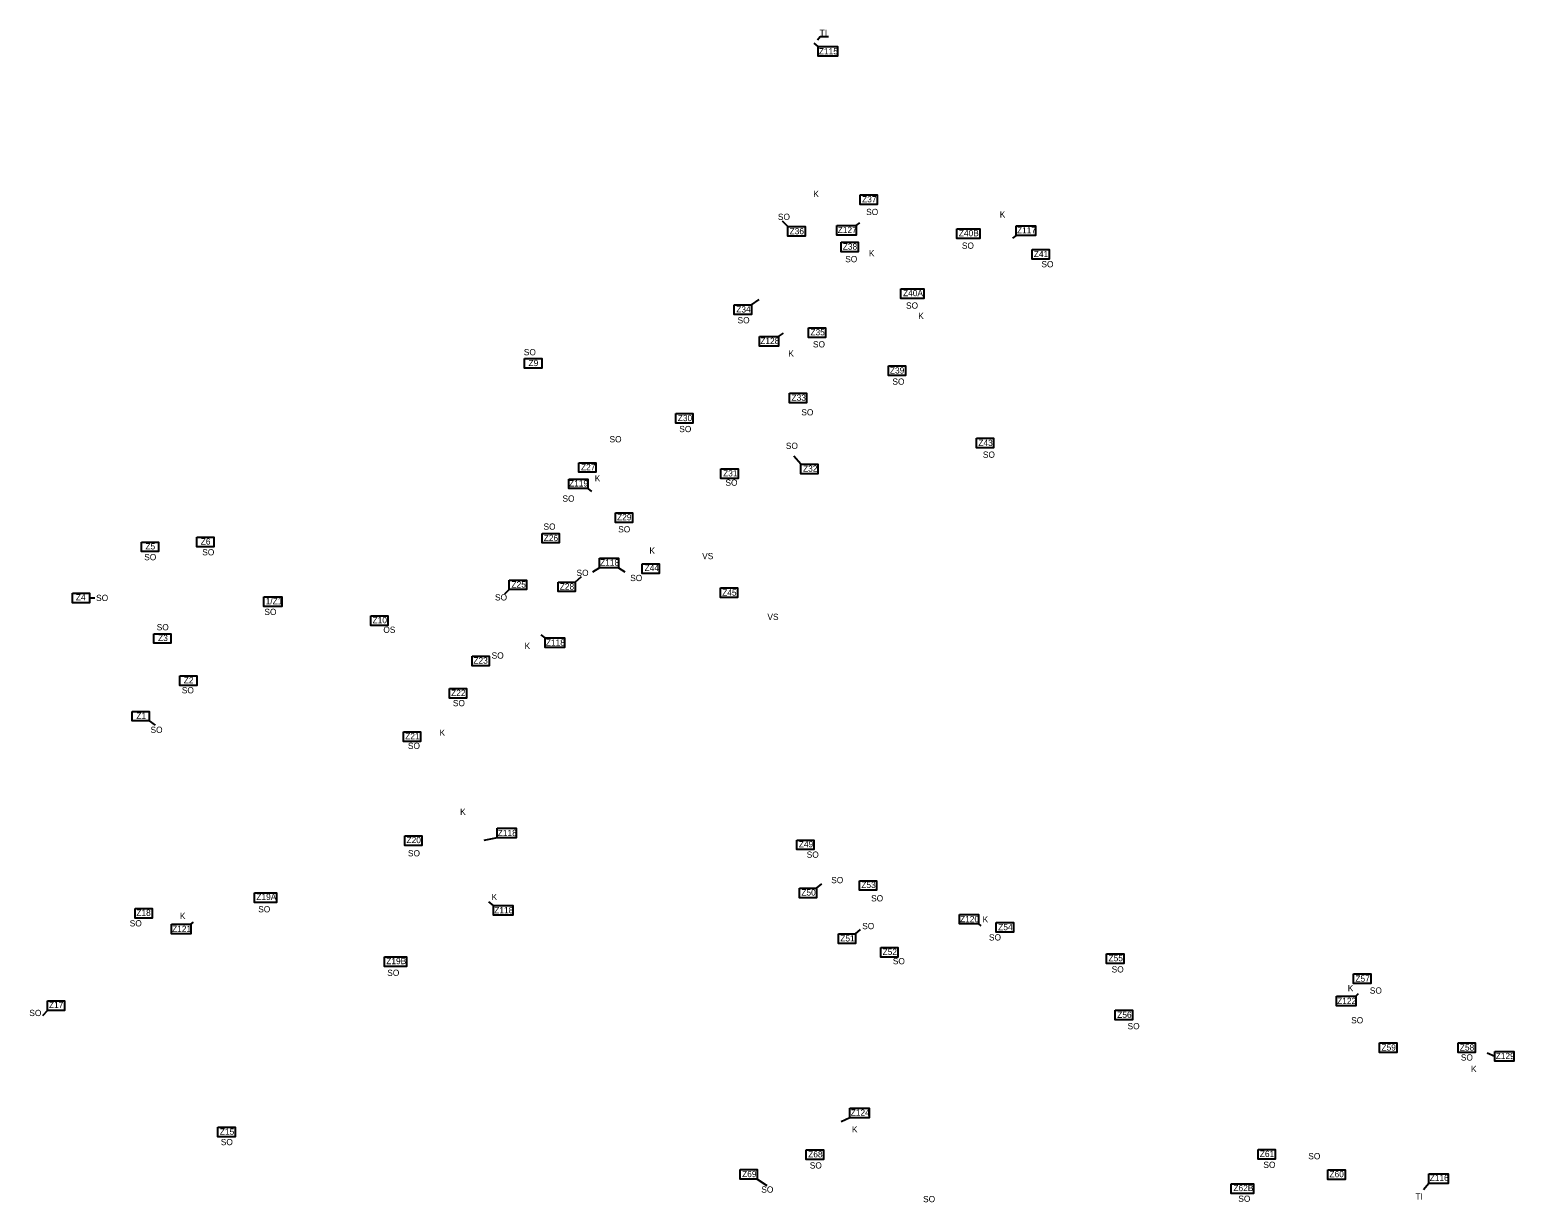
# Model space of a CAD drawing. Extents: x -443485 to -433023, y -1133480 to -1129775.
# Drawn here: x -443043 to -440666, y -1131652 to -1129775 of the extents above; entities that cross this region are included whole.
import ezdxf

# ---------------------------------------------------------------- set-up
doc = ezdxf.new("R2010")
doc.units = 0
for name, color, linetype in [('Vrstva 3', 7, 'Continuous'), ('Vrstva 4', 7, 'Continuous'), ('Vrstva 8', 7, 'Continuous')]:
    doc.layers.add(name, color=color, linetype=linetype)

msp = doc.modelspace()

# ---------------------------------------------------------------- linework, layer by layer
at = {"layer": 'Vrstva 3'}
for p, q in [((-441780.6, -1129802.1), (-441787.2, -1129796.7)), ((-441829.1, -1130090.3), (-441838, -1130081.7)), ((-441808.5, -1130470.4), (-441819.7, -1130457.7)), ((-442169.8, -1130659.1), (-442159.4, -1130650.4)), ((-442275.3, -1130671.3), (-442283.1, -1130678.3)), ((-442947.3, -1130684.5), (-442938.5, -1130684.6)), ((-442851.5, -1130881.4), (-442842.3, -1130888.4)), ((-441783.2, -1131148.9), (-441775.1, -1131141.9)), ((-441721, -1131222.3), (-441712.8, -1131215.4)), ((-443014.7, -1131344.8), (-443022.4, -1131353.5)), ((-441878.2, -1131614.7), (-441862.9, -1131625)), ((-440803, -1131621.5), (-440811.7, -1131631.9))]:
    msp.add_line(p, q, dxfattribs=at)
for points in [[(-441780.6, -1129802.1), (-441749.8, -1129802.1), (-441749.8, -1129817.5), (-441780.6, -1129817.5)], [(-441713.5, -1130039.3), (-441686.2, -1130039.3), (-441686.2, -1130054.7), (-441713.5, -1130054.7)], [(-441829.1, -1130090.3), (-441801.8, -1130090.3), (-441801.8, -1130105.7), (-441829.1, -1130105.7)], [(-441558.8, -1130093.8), (-441522, -1130093.8), (-441522, -1130109.2), (-441558.8, -1130109.2)], [(-441744, -1130115.3), (-441716.6, -1130115.3), (-441716.6, -1130130.7), (-441744, -1130130.7)], [(-441438.1, -1130126.8), (-441410.7, -1130126.8), (-441410.7, -1130142.2), (-441438.1, -1130142.2)], [(-441648.2, -1130189.7), (-441611.5, -1130189.7), (-441611.5, -1130205.1), (-441648.2, -1130205.1)], [(-441915.1, -1130215.4), (-441887.7, -1130215.4), (-441887.7, -1130230.8), (-441915.1, -1130230.8)], [(-441796.3, -1130252.1), (-441768.9, -1130252.1), (-441768.9, -1130267.5), (-441796.3, -1130267.5)], [(-442250.7, -1130301.4), (-442223.3, -1130301.4), (-442223.3, -1130316.8), (-442250.7, -1130316.8)], [(-441668.4, -1130313.2), (-441641, -1130313.2), (-441641, -1130328.6), (-441668.4, -1130328.6)], [(-441826.6, -1130356.8), (-441799.2, -1130356.8), (-441799.2, -1130372.2), (-441826.6, -1130372.2)], [(-442008.5, -1130389.3), (-441981.2, -1130389.3), (-441981.2, -1130404.7), (-442008.5, -1130404.7)], [(-441527.5, -1130428.9), (-441500.2, -1130428.9), (-441500.2, -1130444.3), (-441527.5, -1130444.3)], [(-442163.9, -1130468.1), (-442136.5, -1130468.1), (-442136.5, -1130483.5), (-442163.9, -1130483.5)], [(-441936.4, -1130477.9), (-441909, -1130477.9), (-441909, -1130493.3), (-441936.4, -1130493.3)], [(-441808.5, -1130470.4), (-441781.1, -1130470.4), (-441781.1, -1130485.8), (-441808.5, -1130485.8)], [(-442105.4, -1130548.2), (-442078, -1130548.2), (-442078, -1130563.6), (-442105.4, -1130563.6)], [(-442222.8, -1130581.2), (-442195.5, -1130581.2), (-442195.5, -1130596.5), (-442222.8, -1130596.5)], [(-442864.1, -1130595.1), (-442836.8, -1130595.1), (-442836.8, -1130610.4), (-442864.1, -1130610.4)], [(-442775.7, -1130587.1), (-442748.3, -1130587.1), (-442748.3, -1130602.5), (-442775.7, -1130602.5)], [(-442062.5, -1130629.9), (-442035.1, -1130629.9), (-442035.1, -1130645.2), (-442062.5, -1130645.2)], [(-442275.3, -1130655.9), (-442247.9, -1130655.9), (-442247.9, -1130671.3), (-442275.3, -1130671.3)], [(-442974.7, -1130676.8), (-442947.3, -1130676.8), (-442947.3, -1130692.2), (-442974.7, -1130692.2)], [(-442197.1, -1130659.1), (-442169.8, -1130659.1), (-442169.8, -1130674.5), (-442197.1, -1130674.5)], [(-441937.3, -1130668.5), (-441909.9, -1130668.5), (-441909.9, -1130683.9), (-441937.3, -1130683.9)], [(-442668, -1130682.7), (-442639.5, -1130682.7), (-442639.5, -1130698.1), (-442668, -1130698.1)], [(-442497.1, -1130713.3), (-442469.7, -1130713.3), (-442469.7, -1130728.7), (-442497.1, -1130728.7)], [(-442844.2, -1130741.8), (-442816.9, -1130741.8), (-442816.9, -1130757.2), (-442844.2, -1130757.2)], [(-442334.9, -1130777.7), (-442307.5, -1130777.7), (-442307.5, -1130793.1), (-442334.9, -1130793.1)], [(-442802.8, -1130809.3), (-442775.4, -1130809.3), (-442775.4, -1130824.7), (-442802.8, -1130824.7)], [(-442370.9, -1130829.7), (-442343.6, -1130829.7), (-442343.6, -1130845.1), (-442370.9, -1130845.1)], [(-442878.9, -1130866.1), (-442851.5, -1130866.1), (-442851.5, -1130881.4), (-442878.9, -1130881.4)], [(-442444.7, -1130898.7), (-442417.3, -1130898.7), (-442417.3, -1130914.1), (-442444.7, -1130914.1)], [(-442442.5, -1131065.5), (-442415.2, -1131065.5), (-442415.2, -1131080.9), (-442442.5, -1131080.9)], [(-441815, -1131072), (-441787.6, -1131072), (-441787.6, -1131087.4), (-441815, -1131087.4)], [(-442683.1, -1131156.5), (-442647.9, -1131156.5), (-442647.9, -1131171.9), (-442683.1, -1131171.9)], [(-441810.6, -1131148.9), (-441783.2, -1131148.9), (-441783.2, -1131164.3), (-441810.6, -1131164.3)], [(-441714.8, -1131137.1), (-441687.4, -1131137.1), (-441687.4, -1131152.5), (-441714.8, -1131152.5)], [(-442874.4, -1131181.7), (-442847.1, -1131181.7), (-442847.1, -1131197.1), (-442874.4, -1131197.1)], [(-441495.6, -1131204.2), (-441468.2, -1131204.2), (-441468.2, -1131219.6), (-441495.6, -1131219.6)], [(-441748.4, -1131222.3), (-441721, -1131222.3), (-441721, -1131237.7), (-441748.4, -1131237.7)], [(-441680.5, -1131244), (-441653.2, -1131244), (-441653.2, -1131259.4), (-441680.5, -1131259.4)], [(-442475.1, -1131259.2), (-442439.9, -1131259.2), (-442439.9, -1131274.6), (-442475.1, -1131274.6)], [(-441319, -1131254), (-441291.6, -1131254), (-441291.6, -1131269.4), (-441319, -1131269.4)], [(-440923.5, -1131286.4), (-440896.1, -1131286.4), (-440896.1, -1131301.8), (-440923.5, -1131301.8)], [(-443014.7, -1131329.4), (-442987.3, -1131329.4), (-442987.3, -1131344.8), (-443014.7, -1131344.8)], [(-441305.1, -1131344.5), (-441277.7, -1131344.5), (-441277.7, -1131359.9), (-441305.1, -1131359.9)], [(-440882, -1131396.5), (-440854.6, -1131396.5), (-440854.6, -1131411.9), (-440882, -1131411.9)], [(-440756.3, -1131396.5), (-440728.9, -1131396.5), (-440728.9, -1131411.9), (-440756.3, -1131411.9)], [(-442741.6, -1131531.5), (-442714.2, -1131531.5), (-442714.2, -1131546.9), (-442741.6, -1131546.9)], [(-441799.8, -1131567.7), (-441772.4, -1131567.7), (-441772.4, -1131583.1), (-441799.8, -1131583.1)], [(-441076.4, -1131567.2), (-441049, -1131567.2), (-441049, -1131582.6), (-441076.4, -1131582.6)], [(-441905.5, -1131599.3), (-441878.2, -1131599.3), (-441878.2, -1131614.7), (-441905.5, -1131614.7)], [(-440964.6, -1131599.8), (-440937.2, -1131599.8), (-440937.2, -1131615.2), (-440964.6, -1131615.2)], [(-440803, -1131606.1), (-440772.3, -1131606.1), (-440772.3, -1131621.5), (-440803, -1131621.5)], [(-441119.4, -1131622.2), (-441083.6, -1131622.2), (-441083.6, -1131637.6), (-441119.4, -1131637.6)]]:
    msp.add_lwpolyline(points, close=True, dxfattribs=at)
at = {"layer": 'Vrstva 4'}
msp.add_lwpolyline([(-441764.3, -1129786.7), (-441777.7, -1129786.7), (-441781.9, -1129791.9)], dxfattribs=at)
at = {"layer": 'Vrstva 8'}
for p, q in [((-441720.1, -1130088.6), (-441714.3, -1130084)), ((-441463.6, -1130104.2), (-441469.4, -1130108.5)), ((-441887.7, -1130215.4), (-441875.4, -1130207.1)), ((-441844, -1130266.2), (-441836.1, -1130260.9)), ((-442149.3, -1130509.6), (-442143.6, -1130514.2)), ((-442131, -1130636.5), (-442142.2, -1130643.1)), ((-442100.3, -1130636.5), (-442090.5, -1130642.7)), ((-442217.8, -1130748.4), (-442224.2, -1130743.6)), ((-442294.8, -1131068.6), (-442315.9, -1131072.6)), ((-442300.3, -1131176.7), (-442308.1, -1131170.8)), ((-442785.3, -1131206.9), (-442780.8, -1131203.4)), ((-441523.9, -1131206.4), (-441520.2, -1131209.2)), ((-440920.2, -1131322), (-440915.5, -1131317.9)), ((-440697.5, -1131418.4), (-440709.9, -1131413.3)), ((-441730.1, -1131516.6), (-441743.7, -1131522.9))]:
    msp.add_line(p, q, dxfattribs=at)
for points in [[(-441750.9, -1130088.6), (-441720.1, -1130088.6), (-441720.1, -1130104), (-441750.9, -1130104)], [(-441463.6, -1130088.8), (-441432.8, -1130088.8), (-441432.8, -1130104.2), (-441463.6, -1130104.2)], [(-441874.8, -1130266.2), (-441844, -1130266.2), (-441844, -1130281.6), (-441874.8, -1130281.6)], [(-442180.1, -1130494.2), (-442149.3, -1130494.2), (-442149.3, -1130509.6), (-442180.1, -1130509.6)], [(-442131, -1130621.1), (-442100.3, -1130621.1), (-442100.3, -1130636.5), (-442131, -1130636.5)], [(-442217.8, -1130748.4), (-442187, -1130748.4), (-442187, -1130763.8), (-442217.8, -1130763.8)], [(-442294.8, -1131053.2), (-442264, -1131053.2), (-442264, -1131068.6), (-442294.8, -1131068.6)], [(-442300.3, -1131176.7), (-442269.5, -1131176.7), (-442269.5, -1131192.1), (-442300.3, -1131192.1)], [(-441554.7, -1131191), (-441523.9, -1131191), (-441523.9, -1131206.4), (-441554.7, -1131206.4)], [(-442816.1, -1131206.9), (-442785.3, -1131206.9), (-442785.3, -1131222.3), (-442816.1, -1131222.3)], [(-440951, -1131322), (-440920.2, -1131322), (-440920.2, -1131337.4), (-440951, -1131337.4)], [(-440697.5, -1131410.7), (-440666.8, -1131410.7), (-440666.8, -1131426.1), (-440697.5, -1131426.1)], [(-441730.1, -1131501.3), (-441699.3, -1131501.3), (-441699.3, -1131516.7), (-441730.1, -1131516.7)]]:
    msp.add_lwpolyline(points, close=True, dxfattribs=at)

# ---------------------------------------------------------------- texts
at = {"layer": 'Vrstva 3'}
for s, p in [('Z115', (-441779.6, -1129814.6)), ('Z37', (-441710.4, -1130051.5)), ('Z36', (-441826.5, -1130102.5)), ('Z40B', (-441555.5, -1130105.7)), ('Z38', (-441741.3, -1130127.2)), ('Z41', (-441435.5, -1130139.1)), ('Z40A', (-441644.9, -1130201.6)), ('Z34', (-441911.9, -1130227.7)), ('Z35', (-441793.1, -1130264.3)), ('Z9', (-442244.4, -1130313.5)), ('Z39', (-441665.9, -1130325.4)), ('Z33', (-441823.4, -1130369)), ('Z30', (-442005.5, -1130401.6)), ('Z43', (-441524.3, -1130441.2)), ('Z27', (-442160.4, -1130480.1)), ('Z31', (-441932.9, -1130490.1)), ('Z32', (-441805, -1130482.6)), ('Z29', (-442102.7, -1130560.4)), ('Z26', (-442220.1, -1130593.6)), ('Z5', (-442857.7, -1130606.9)), ('Z6', (-442769.2, -1130599.2)), ('Z44', (-442058.6, -1130641.4)), ('Z25', (-442271.7, -1130668)), ('Z4', (-442969.1, -1130688.5)), ('Z28', (-442194.4, -1130671.3)), ('Z45', (-441934.4, -1130681)), ('1/Z1', (-442665.2, -1130694.6)), ('Z10', (-442494.1, -1130725)), ('Z3', (-442837.5, -1130753.5)), ('Z23', (-442332.7, -1130789.7)), ('Z2', (-442796.3, -1130821.1)), ('Z22', (-442368.4, -1130841.6)), ('Z1', (-442872.3, -1130878.1)), ('Z21', (-442441.8, -1130910.7)), ('Z20', (-442439.7, -1131077)), ('Z49', (-441811.7, -1131083.8)), ('Z50', (-441807.7, -1131160.9)), ('Z53', (-441711.7, -1131148.8)), ('Z19A', (-442680.2, -1131168)), ('Z18', (-442872.3, -1131193.4)), ('Z51', (-441745.4, -1131234.4)), ('Z54', (-441492.5, -1131216.4)), ('Z52', (-441677.6, -1131256)), ('Z19B', (-442472.2, -1131270.7)), ('Z55', (-441315.9, -1131266)), ('Z57', (-440920.7, -1131298.8)), ('Z17', (-443012.2, -1131341)), ('Z56', (-441302, -1131356.6)), ('Z59', (-440878.9, -1131409)), ('Z58', (-440753.5, -1131409)), ('Z15', (-442738.6, -1131543.7)), ('Z68', (-441796.7, -1131580)), ('Z61', (-441073.7, -1131579.4)), ('Z69', (-441902.5, -1131611.6)), ('Z60', (-440962.2, -1131611.7)), ('Z116', (-440801.8, -1131617.8)), ('Z62B', (-441116, -1131634))]:
    msp.add_text(s, height=10, dxfattribs=at).set_placement(p)
at = {"layer": 'Vrstva 4'}
for s, p in [('TI', (-441778.4, -1129785.1)), ('K', (-441788.5, -1130042.9)), ('SO', (-441703.9, -1130071.8)), ('SO', (-441845.2, -1130079.6)), ('K', (-441490.1, -1130075.8)), ('K', (-441699.6, -1130137.8)), ('SO', (-441550.7, -1130125.7)), ('SO', (-441737.5, -1130147.2)), ('SO', (-441423.4, -1130155.4)), ('SO', (-441640.1, -1130221.6)), ('K', (-441620.6, -1130238.2)), ('SO', (-441909.8, -1130245.1)), ('SO', (-441789.1, -1130283.6)), ('SO', (-442252, -1130296.2)), ('K', (-441828.5, -1130298.3)), ('SO', (-441661.9, -1130343.3)), ('SO', (-441807.7, -1130392.4)), ('SO', (-442003.1, -1130419.2)), ('SO', (-442114.8, -1130435.6)), ('SO', (-441832.5, -1130446.1)), ('SO', (-441517.1, -1130460.2)), ('K', (-442138.4, -1130498.1)), ('SO', (-441929.2, -1130505)), ('SO', (-442190.1, -1130530.5)), ('SO', (-442220.5, -1130575.4)), ('SO', (-442100.9, -1130579.7)), ('SO', (-442766.8, -1130616.4)), ('K', (-442050.9, -1130613.8)), ('SO', (-442859.7, -1130624.2)), ('VS', (-441966.5, -1130622.5)), ('SO', (-442167.6, -1130649.4)), ('SO', (-442081.7, -1130657.6)), ('SO', (-442936.7, -1130689.5)), ('SO', (-442298.1, -1130688.6)), ('SO', (-442667.3, -1130711.9)), ('SO', (-442839.7, -1130736.4)), ('VS', (-441862, -1130719.8)), ('OS', (-442476.9, -1130740.4)), ('SO', (-442303.5, -1130781.7)), ('K', (-442250.7, -1130766.3)), ('SO', (-442799.5, -1130837.3)), ('SO', (-442365.6, -1130857.8)), ('SO', (-442849.6, -1130900.6)), ('K', (-442386.9, -1130905.2)), ('SO', (-442437.5, -1130926.3)), ('K', (-442354, -1131031.8)), ('SO', (-442437.5, -1131098.2)), ('SO', (-441799.1, -1131100.4)), ('SO', (-441759.9, -1131141.1)), ('SO', (-442677.2, -1131187.8)), ('K', (-442303.6, -1131168.2)), ('SO', (-441696, -1131170.3)), ('SO', (-442882.9, -1131210.3)), ('K', (-442802.6, -1131198.5)), ('SO', (-441710.3, -1131214.7)), ('K', (-441517.4, -1131204)), ('SO', (-441507.3, -1131232.8)), ('SO', (-441661.3, -1131270.8)), ('SO', (-441310.9, -1131284)), ('SO', (-442470.6, -1131289.5)), ('K', (-440932.9, -1131314.1)), ('SO', (-440897.6, -1131317.9)), ('SO', (-443043.6, -1131353.8)), ('SO', (-441285.4, -1131374.9)), ('SO', (-440927.5, -1131365.5)), ('SO', (-440751.9, -1131425)), ('K', (-440735.6, -1131443.4)), ('K', (-441726.6, -1131540.1)), ('SO', (-442737.1, -1131560.4)), ('SO', (-440996.1, -1131583)), ('SO', (-441794.2, -1131597.8)), ('SO', (-441068, -1131596.8)), ('SO', (-441871.8, -1131636.4)), ('SO', (-441612.8, -1131651.7)), ('SO', (-441108.1, -1131651.1)), ('TI', (-440824.7, -1131647.6))]:
    msp.add_text(s, height=10, dxfattribs=at).set_placement(p)
at = {"layer": 'Vrstva 8'}
for s, p in [('Z127', (-441749.5, -1130100.6)), ('Z117', (-441462.5, -1130101.2)), ('Z128', (-441873.4, -1130278.2)), ('Z119', (-442179.6, -1130506.2)), ('Z118', (-442129.9, -1130632.9)), ('Z118', (-442216.7, -1130760.9)), ('Z118', (-442293.7, -1131065.7)), ('Z118', (-442299.3, -1131189.2)), ('Z120', (-441553.6, -1131203.5)), ('Z121', (-442815.1, -1131219.3)), ('Z122', (-440949.9, -1131334.5)), ('Z129', (-440696.1, -1131422.7)), ('Z124', (-441728.7, -1131513.3))]:
    msp.add_text(s, height=10, dxfattribs=at).set_placement(p)

doc.saveas('drawing.dxf')
